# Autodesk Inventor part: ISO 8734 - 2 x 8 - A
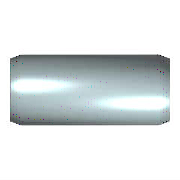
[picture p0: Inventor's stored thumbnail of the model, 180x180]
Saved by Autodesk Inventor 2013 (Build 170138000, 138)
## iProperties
IsCustomPart: 0
Created: 2012-02
Part Number: ISO 8734 - 2 x 8 - A
Material: Stahl
Description: Zylinderstift
Document SubType Name: Modeling
Standard: ISO 8734
Designer: rYan
Standards Organization: DIN
Language: de-DE
Size Designation: 2 x 8 - A
Categories: <MemberInstance><Categories><Category DisplayName="Verbindungselemente" InternalName="e4da775c-781d-43d5-af7c-5136215cf5a6" Mnemonic="FSTN"><Category DisplayNam
Density: 7.85 g/cm^3
Mass: 0.195724 g
Surface Area: 0.553671 cm^2
Volume: 0.024933 cm^3
Author: rYan
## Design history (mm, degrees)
sketch "Skizze"
  geometry: C1 r 1 at (0, 0); 1 further point
  constraints: 1 centre point, 1 coincident
  dimensions: "d1" = 2 diameter of C1 (= NND)
extrude "Körper" new body sketch "Skizze" distance "d2" = 8 (= NLG); taper "d3" = 0 deg
body "Solid1"
chamfer "Fase1" distance "d4" = 0.35 (= PHH); stored, may be unused: angle "d5" = 15 deg (= FAWI), second distance "d11" = 0.35 (= PHH)
chamfer "Fase2" distance "d8" = 0.35 (= PHH); stored, may be unused: angle "d9" = 15 deg (= FAWI), second distance "d12" = 0.35 (= PHH)
other parameters: "NND" = 2 [user parameter; used in 1 equation term], "NLG" = 8 [user parameter; used in 1 equation term], "PHH" = 0.35 [user parameter; used in 5 equation terms], "FAWI" = 15 deg [user parameter; used in 2 equation terms], "d13" = 0, "d15" = 0, "d16" = 0, "PHH2" = 0.35 (= PHH) [user parameter], "FAWI2" = 15 deg [user parameter]
